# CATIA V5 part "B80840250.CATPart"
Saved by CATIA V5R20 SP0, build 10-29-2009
Part number: B80840250
Revision: 3
Definition: design
Nomenclature: B80840250
Source: made
Description: NOT SPECIFIED
Bounding box of the stored display mesh (mm): x -22.5 to 22.5, y -22.5 to 22.5, z 0 to 250
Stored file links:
  C:\Users\Raffaele\Desktop\3D X SITO CF\BOLEX\4-PILLAR REF 808\B80840250.CATPart
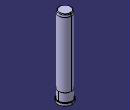
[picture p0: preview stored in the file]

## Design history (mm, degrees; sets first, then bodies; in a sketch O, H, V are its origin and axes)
Body1 "MANIFOLD_SOLID_BREP #450" (main body)
  Solid1: solid without history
